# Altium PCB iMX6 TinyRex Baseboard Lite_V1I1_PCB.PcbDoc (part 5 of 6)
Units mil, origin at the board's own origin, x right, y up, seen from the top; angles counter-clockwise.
Board outline 3149.61 x 3543.31 mil, 6 copper layers (L1, L2, L3, L4 (PWR), L5, L6), stack 60.634 mil thick; 385 components, 309 nets, 1566 pads, 914 vias.
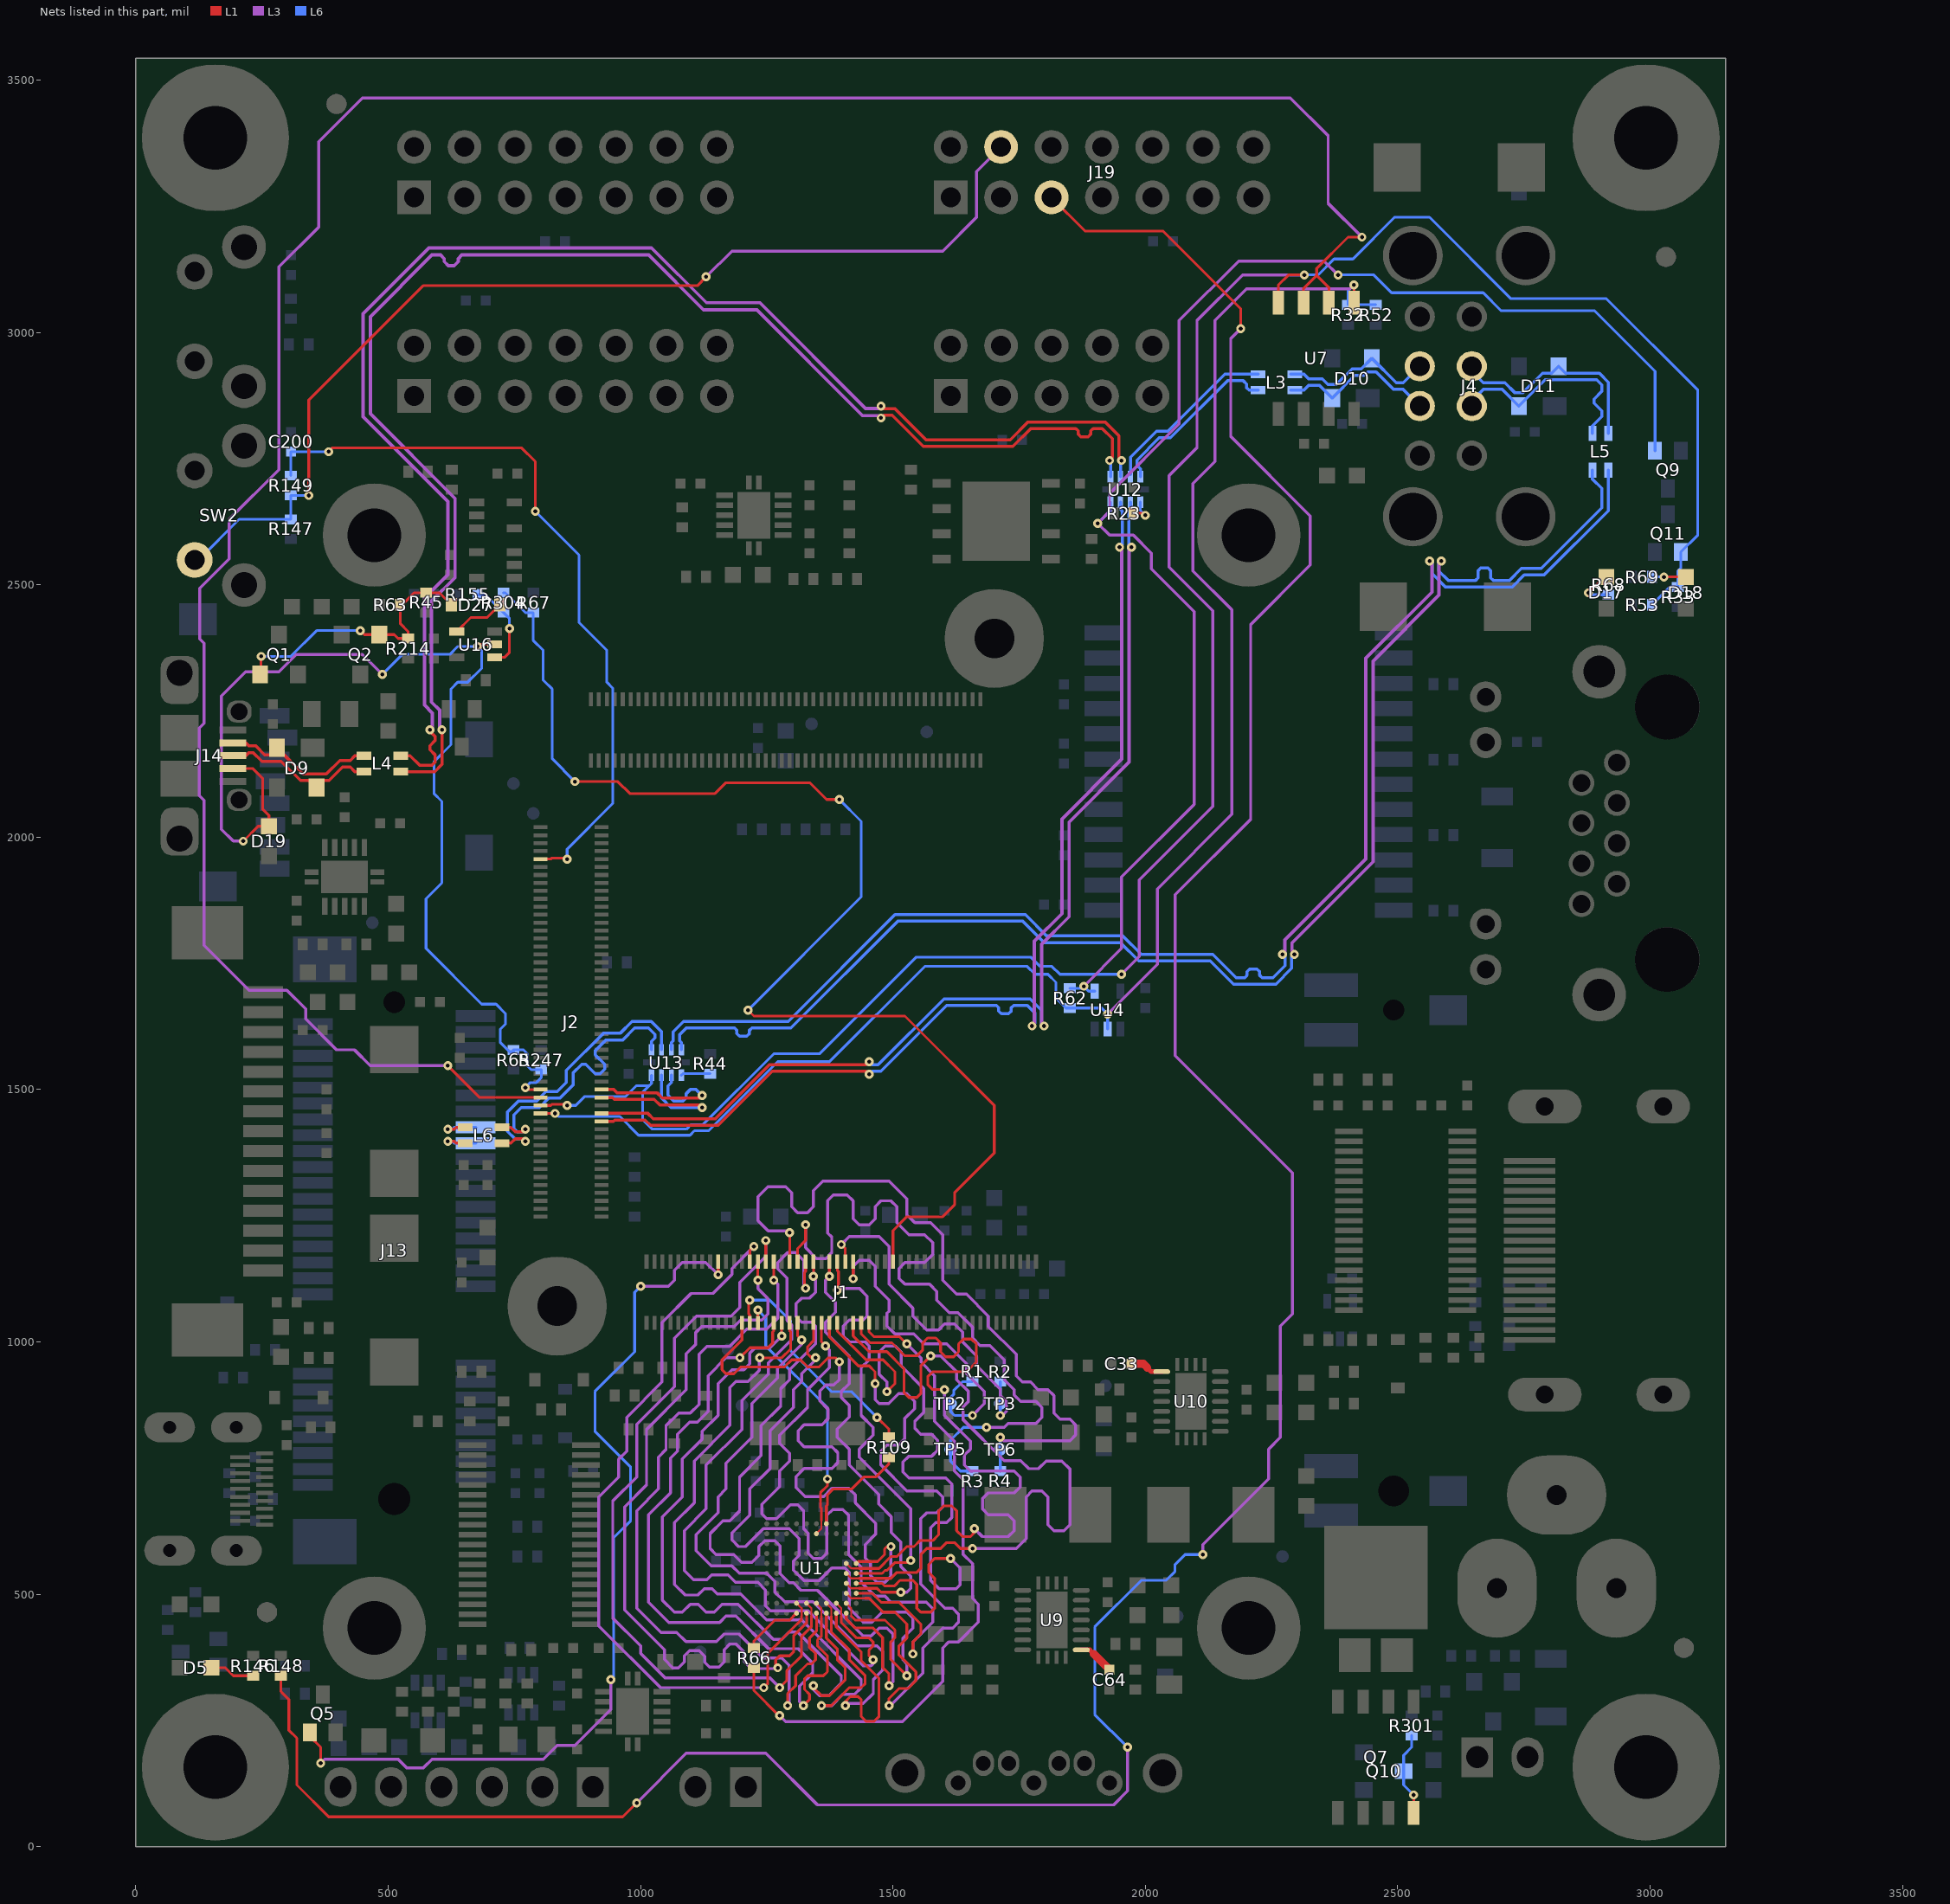
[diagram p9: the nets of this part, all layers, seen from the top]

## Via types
v1: diameter 17.72, hole 7.87, L1 to L6, 471 vias
v2: diameter 17.72, hole 7.87, L1 to L6, tented both sides, 442 vias
v3: diameter 17.72, hole 7.87, L1 to L6, tented top, 1 vias

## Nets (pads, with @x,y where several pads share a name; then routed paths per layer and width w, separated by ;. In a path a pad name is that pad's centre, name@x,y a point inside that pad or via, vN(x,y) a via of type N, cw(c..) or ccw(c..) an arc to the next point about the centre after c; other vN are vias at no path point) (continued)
USB0_CON_N: D10.2 J4.6 L3.2 | length 319
  L6 w6: L3.2@2288.39,2885.83 L3.2@2296.26,2885.83 2314.22,2885.83 2323.48,2895.08 2345.08,2895.08 D10.2@2370.08,2870.08 2414.83,2914.83 2433.2,2914.83 2440.37,2922 2457.27,2922 2492.06,2887.2 2510.82,2887.2 J4.6@2543.7,2854.33
USB0_CON_P: D10.4 J4.7 L3.1 | length 319
  L6 w6: L3.1@2288.39,2917.32 L3.1@2296.26,2917.32 2314.22,2917.32 2323.48,2908.07 2350.46,2908.07 2361.63,2896.9 2378.53,2896.9 2409.45,2927.82 2427.82,2927.82 D10.4@2448.82,2948.82 2497.44,2900.19 2510.82,2900.19 J4.7@2543.7,2933.07
USB0_ID: D19.1 J2.68 J14.4 R65.1 R247.2 U16.2 | length 2318.3
  L1 w5.4: J14.4@187.99,2135.83 J14.4@191.93,2135.83 232.03,2135.83 251.08,2116.77 251.08,2056 263.78,2043.31 D19.1@263.78,2021.65 242.13,2021.65 v1(212.6,1992.13) ; v1(677.17,2377.95) 681.1,2381.89 U16.2@710.63,2381.89 ; v1(771.65,1503.94) 775.59,1500 J2.68@801.57,1500
  L3 w5.9: v1(212.6,1992.13) 192.91,1992.13 169.29,2015.75 169.29,2279.53 217.72,2327.95 283.46,2327.95 317.72,2362.2 448.82,2362.2 v1(488.19,2322.83)
  L6 w5.4: v1(488.19,2322.83) 527.56,2362.2 622.05,2362.2 637.8,2377.95 v1(677.17,2377.95) 685.04,2370.08 685.04,2334.65 657.48,2307.09 637.8,2307.09 624.21,2293.5 624.21,2183.27 590.55,2149.61 590.55,2086.61 606.3,2070.87 606.3,1909.45 574.8,1877.95 574.8,1779.53 685.04,1669.29 713.59,1669.29 732.28,1650.6 732.28,1629.92 722.24,1619.88 722.24,1592.72 740.16,1574.8 R65.1@748.03,1574.8 ; R65.1@748.03,1578.74 767.72,1578.74 775.59,1570.87 775.59,1547.24 783.46,1539.37 R247.2@803.15,1539.37 803.15,1523.62 793.31,1513.78 781.5,1513.78 v1(771.65,1503.94)
USB0_ID_BUFF: D27.1 U16.4 | length 107.4
  L1 w5.4: U16.4@635.83,2407.48 663.58,2435.24 695.83,2435.24 D27.1@721.23,2460.63
USB0_ID_BUFF_EN: J1.38 R67.2 R304.2 | length 2529.1
  L1 w5.4: v1(870.08,2110.24) 954.98,2110.24 978.6,2086.61 1147.38,2086.61 1168.84,2108.07 1335.1,2108.07 1368.37,2074.8 v1(1393.7,2074.8) ; v1(1212.6,1657.48) 1224.41,1645.67 1523.62,1645.67 1700.79,1468.5 1700.79,1374.41 1622.05,1295.67 1622.05,1271.65 1598.43,1248.03 1527.56,1248.03 1500,1220.47 J1.38@1500,1159.06
  L6 w5.4: R304.2@728.35,2484.25 732.28,2484.25 771.65,2444.88 R67.2@787.4,2444.88 787.4,2389.76 807.09,2370.08 807.09,2311.02 825,2293.11 825,2155.31 v1(870.08,2110.24) ; v1(1212.6,1657.48) 1437.01,1881.89 1437.01,2031.5 v1(1393.7,2074.8)
USB0_ID_BUFF_EN_R: R155.1 R304.1 U16.1 | length 183.1
  L1 w5.4: U16.1@710.63,2356.3 730.31,2356.3 740.16,2366.14 v1(740.16,2413.39)
  L6 w5.4: R155.1@677.17,2480.31 692.91,2480.31 R304.1@728.35,2444.88 740.16,2433.07 v1(740.16,2413.39)
USB0_L_N: L3.3 U12.4 | length 352.7
  L6 w6: U12.4@1990.16,2714.16 1990.16,2729.57 1983.51,2736.22 1983.51,2747.29 2027.56,2791.34 2049.87,2791.34 2162.86,2904.33 2194.09,2904.33 2200.79,2897.64 2200.79,2890.5 2205.46,2885.83 L3.3@2223.43,2885.83
USB0_L_P: L3.4 U12.3 | length 354.7
  L6 w6: U12.3@1970.52,2719.04 1970.52,2752.67 2022.18,2804.33 2044.49,2804.33 2157.48,2917.32 L3.4@2223.43,2917.32
USB0_N: J2.73 U12.7 | length 2138.7
  L1 w6: J2.73@922.83,1452.76 1014.43,1452.76 1025.07,1442.12 1148.16,1442.12 1255.18,1549.14 1446.78,1549.14 v2(1452.76,1555.12)
  L3 w6.7: v2(1799.21,1625.98) 1794.55,1630.65 1794.55,1788.08 1848.95,1842.48 1848.95,2030.05 1967.78,2148.88 1967.78,2570.14 v2(1972.44,2574.8)
  L6 w6: v2(1452.76,1555.12) 1458.73,1549.14 1470.4,1549.14 1600.98,1679.72 1771.59,1679.72 1793.9,1657.42 1793.9,1631.3 v2(1799.21,1625.98) ; U12.7@1970.47,2663.79 1970.47,2649.37 1967.12,2646.02 1967.12,2580.12 v2(1972.44,2574.8)
USB0_P: J2.75 U12.8 | length 2139.5
  L1 w6: J2.75@922.83,1437.01 946.21,1437.01 948.97,1439.77 1009.05,1439.77 1019.69,1429.13 1153.54,1429.13 1260.56,1536.15 1446.78,1536.15 v2(1452.76,1530.18)
  L3 w6.7: v2(1775.59,1625.98) 1780.25,1630.65 1780.25,1794.01 1834.65,1848.4 1834.65,2035.97 1953.48,2154.81 1953.48,2570.14 v2(1948.82,2574.8)
  L6 w6: v2(1452.76,1530.18) 1458.73,1536.15 1475.79,1536.15 1606.36,1666.73 1704.72,1666.73 1709.38,1662.07 1709.38,1655.67 1714.83,1650.22 1729.07,1650.22 1734.51,1655.67 1734.51,1662.07 1739.17,1666.73 1766.21,1666.73 1780.91,1652.03 1780.91,1631.3 v2(1775.59,1625.98) ; v2(1948.82,2574.8) 1954.13,2580.12 1954.13,2646.02 1950.79,2649.37 U12.8@1950.79,2663.79
USB0_PWR_EN: J2.74 R32.1 R52.2 R62.1 U7.1 U14.2 | length 3332.7
  L1 w5.4: J2.74@801.57,1452.76 v2(830.71,1452.76) ; U7.1@2413.58,3059.06 v2@2413.58,3094.49
  L3 w5.9: v2(1925.2,1649.61) 2023.62,1748.03 2023.62,1897.64 2171.26,2045.28 2171.26,2450.79 2094.49,2527.56 2094.49,2700.79 2137.8,2744.09 2137.8,3023.62 2200.79,3086.61 2405.51,3086.61 v2(2413.39,3094.49)
  L6 w5.4: v2(830.71,1452.76) 836.81,1446.65 958.86,1446.65 996.06,1409.45 1097.7,1409.45 1106.75,1418.5 1135.04,1418.5 1271.65,1555.12 1374.02,1555.12 1562.99,1744.09 1766.01,1744.09 1781.75,1728.35 1807.09,1728.35 1822.83,1712.6 1822.83,1681.1 1842.52,1661.42 R62.1@1850.39,1661.42 1913.39,1661.42 v2(1925.2,1649.61) U14.2@1925.2,1620.08 ; v2(2413.39,3094.49) 2401.57,3082.68 R32.1@2401.57,3055.12 R52.2@2456.69,3055.12
USB0_SW_CTRL: Q9.1 R62.2 U12.9 U14.4 | length 2930.1
  L3 w5.9: v2(1877.95,1704.72) 1952.76,1779.53 1952.76,1921.26 2096.46,2064.96 2096.46,2446.85 2011.81,2531.5 2011.81,2562.99 1976.38,2598.43 1929.13,2598.43 v2(1905.51,2622.05) 1929.13,2645.67 1929.13,2681.1 2066.93,2818.9 2066.93,3023.62 2185.04,3141.73 2354.33,3141.73 v2(2381.89,3114.17)
  L6 w5.4: R62.2@1850.39,1700.79 1874.02,1700.79 v2(1877.95,1704.72) 1887.8,1694.88 U14.4@1899.61,1694.88 ; v2(1905.51,2622.05) 1931.1,2647.64 U12.9@1931.1,2663.79 ; v2(2381.89,3114.17) 2452.56,3114.17 2487.99,3078.74 2669.29,3078.74 2704.72,3043.31 2889.76,3043.31 3009.84,2923.23 Q9.1@3009.84,2765.75
USB0_SW_CTRLN_RED: D17.1 R68.1 | length 89.5
  L1 w5.4: v1(2877.95,2484.25) 2909.45,2515.75 D17.1@2913.39,2515.75
  L6 w5.4: v1(2877.95,2484.25) 2881.89,2480.31 R68.1@2917.32,2480.31
USB0_SW_EN: R23.2 U12.6 | length 55.3
  L1 w5.4: R23.2@1976.38,2641.73 1996.06,2641.73 v2(2000,2637.8)
  L6 w5.4: U12.6@1990.16,2663.79 1990.16,2647.64 v2(2000,2637.8)
USB1_CON_N: D11.2 J4.2 L5.1 | length 433
  L6 w6: J4.2@2646.85,2854.33 2646.85,2864.76 2669.29,2887.2 2707.22,2887.2 D11.2@2740.16,2854.33 D11.2@2740.16,2854.33 2792.08,2906.25 2894.28,2906.25 2904.33,2896.19 2904.33,2883.66 2888.78,2868.11 2888.78,2860.04 2904.33,2844.49 2904.33,2833.47 2885.83,2814.96 L5.1@2885.83,2800.2
USB1_CON_P: D11.4 J4.3 L5.2 | length 434
  L6 w6: J4.3@2646.85,2933.07 2646.85,2922.64 2669.29,2900.19 2712.6,2900.19 2731.64,2881.15 2748.61,2881.15 2786.7,2919.24 2805.07,2919.24 D11.4@2818.9,2933.07 2832.73,2919.24 2899.66,2919.24 2917.32,2901.57 L5.2@2917.32,2800.2
USB1_L_N: L5.4 U13.4 | length 2888.4
  L3 w6.7: v2(2295.28,1767.72) 2290.61,1772.38 2290.61,1790.61 2451.31,1951.31 2451.31,2348.95 2581.95,2479.59 2581.95,2542.58 v2(2586.61,2547.24)
  L6 w6: U13.4@1080.71,1578.86 1080.71,1593.27 1077.36,1596.62 1077.36,1608.86 1090.55,1622.05 1186.02,1622.05 1190.68,1617.39 1190.68,1610.98 1196.13,1605.54 1210.37,1605.54 1215.81,1610.98 1215.81,1617.39 1220.47,1622.05 1297.9,1622.05 1509.32,1833.47 1757.08,1833.47 1799.21,1791.34 1950.13,1791.34 1986.75,1754.73 2128.48,1754.73 2174.54,1708.66 2258.53,1708.66 2289.96,1740.09 2289.96,1762.4 v2(2295.28,1767.72) ; v2(2586.61,2547.24) 2581.3,2541.93 2581.3,2527.56 2599.8,2509.05 2654.53,2509.05 2659.19,2513.71 2659.19,2527.99 2664.63,2533.44 2678.87,2533.44 2684.32,2527.99 2684.32,2513.71 2688.98,2509.05 2721.65,2509.05 2745.27,2532.68 2784.64,2532.68 2904.33,2652.36 2904.33,2691.09 2885.83,2709.6 L5.4@2885.83,2727.36
USB1_L_P: L5.3 U13.3 | length 2887.8
  L3 w6.7: v2(2271.65,1767.72) 2276.31,1772.38 2276.31,1796.54 2437.01,1957.23 2437.01,2354.87 2567.65,2485.51 2567.65,2542.58 v2(2562.99,2547.24)
  L6 w6: U13.3@1061.02,1578.86 1061.02,1593.27 1064.37,1596.62 1064.37,1614.24 1085.17,1635.04 1292.52,1635.04 1503.94,1846.46 1762.47,1846.46 1804.59,1804.33 1955.51,1804.33 1992.13,1767.72 2133.86,1767.72 2179.92,1721.65 2196.85,1721.65 2201.51,1726.31 2201.51,1733.23 2206.95,1738.67 2221.2,1738.67 2226.64,1733.23 2226.64,1726.31 2231.3,1721.65 2253.15,1721.65 2276.97,1745.47 2276.97,1762.4 v2(2271.65,1767.72) ; v2(2562.99,2547.24) 2568.31,2541.93 2568.31,2522.18 2594.42,2496.06 2727.03,2496.06 2750.65,2519.69 2790.02,2519.69 2917.32,2646.98 L5.3@2917.32,2727.36
USB1_N: J2.67 U13.7 | length 342
  L1 w6: J2.67@922.83,1500 947.04,1500 953.19,1493.85 1032.33,1493.85 1043.31,1482.87 1116.73,1482.87 v2(1122.05,1488.19)
  L6 w6: U13.7@1061.02,1528.48 1061.02,1514.07 1054.33,1507.37 1054.33,1488.98 1065.75,1477.56 1083.86,1477.56 1090.55,1484.25 1090.55,1492.13 1098.43,1500 1110.24,1500 v2(1122.05,1488.19)
USB1_P: J2.69 U13.8 | length 340.8
  L1 w6: J2.69@922.83,1484.25 944.41,1484.25 947.81,1480.86 1026.95,1480.86 1037.93,1469.88 1116.73,1469.88 v2(1122.05,1464.57)
  L6 w6: U13.8@1041.34,1528.48 1041.34,1483.6 1060.37,1464.57 v2(1122.05,1464.57)
USB1_PWR_EN: J2.72 Q11.1 R33.1 R53.2 U7.4 U13.9 | length 4672.4
  L1 w5.4: J2.72@801.57,1468.5 821.91,1468.5 824.08,1470.67 852.17,1470.67 v2(854.33,1468.5) ; U7.4@2263.58,3047.44 U7.4@2263.58,3059.06 2263.58,3094.29 2283.46,3114.17 v2(2314.96,3114.17)
  L3 w5.9: v2(1952.76,1728.35) 1988.19,1763.78 1988.19,1915.38 2133.86,2061.04 2133.86,2448.82 2047.24,2535.43 2047.24,2716.54 2102.36,2771.65 2102.36,3023.62 2192.91,3114.17 v2(2314.96,3114.17)
  L6 w5.4: v2(854.33,1468.5) 871.52,1468.5 889.43,1486.42 970.67,1486.42 992.13,1507.87 1017.52,1507.87 ; U13.9@1021.65,1528.48 1021.65,1512.01 1017.52,1507.87 ; v2@1948.82,1724.41 v2(1952.76,1728.35) 1830.71,1728.35 1814.96,1744.09 1791.73,1744.09 1773.82,1762.01 1545.47,1762.01 1354.33,1570.87 1263.78,1570.87 1123.62,1430.71 1100,1430.71 1090.94,1421.65 1023.23,1421.65 1003.94,1440.94 1003.94,1494.29 1017.52,1507.87 ; v2(2314.96,3114.17) 2342.52,3114.17 2374.02,3145.67 2411.16,3145.67 2493.84,3228.35 2562.99,3228.35 2724.41,3066.93 2913.39,3066.93 3094.49,2885.83 3094.49,2598.43 Q11.1@3061.02,2564.96 3061.02,2533.46 3055.12,2527.56 R33.1@3055.12,2496.06 3039.37,2496.06 R53.2@3003.94,2460.63
USB1_PWR_ENN_RED: D18.1 R69.1 | length 66.9
  L1 w5.4: v1(3027.56,2515.75) D18.1@3070.87,2515.75
  L6 w5.4: R69.1@3003.94,2515.75 v1(3027.56,2515.75)
USB1_SW_EN: R44.2 U13.6 | length 58.3
  L6 w5.4: U13.6@1080.71,1528.48 1083.72,1531.5 R44.2@1137.8,1531.5
USB_MPCIE_CON_N: J13.36 L6.2 | length 92.8
  L1 w6: v1(618.11,1397.64) 630.66,1397.64 634.6,1393.7 L6.2@652.56,1393.7
  L6 w6: v1(618.11,1397.64) 626.72,1397.64 630.66,1393.7 J13.36@673.23,1393.7
USB_MPCIE_CON_P: J13.38 L6.1 | length 92.8
  L1 w6: v1(618.11,1421.26) 630.66,1421.26 634.6,1425.2 L6.1@652.56,1425.2
  L6 w6: v1(618.11,1421.26) 626.72,1421.26 630.66,1425.2 J13.38@673.23,1425.2
USB_MPCIE_N: L6.3 U13.2 | length 571.9
  L1 w6: L6.3@725.39,1393.7 743.16,1393.7 752.41,1402.95 766.34,1402.95 v2(771.65,1397.64)
  L6 w6: v2(771.65,1397.64) 766.34,1402.95 750.53,1402.95 736.22,1417.26 736.22,1455.38 758.4,1477.56 794.22,1477.56 812.59,1495.93 834.91,1495.93 853.02,1514.04 853.02,1538.06 926.38,1611.42 959.37,1611.42 982.99,1635.04 1021.13,1635.04 1041.34,1614.83 U13.2@1041.34,1578.86
USB_MPCIE_P: L6.4 U13.1 | length 573.4
  L1 w6: L6.4@725.39,1425.2 743.16,1425.2 752.41,1415.94 766.34,1415.94 v2(771.65,1421.26)
  L6 w6: v2(771.65,1421.26) 766.34,1415.94 755.91,1415.94 749.21,1422.64 749.21,1450 763.78,1464.57 799.6,1464.57 817.97,1482.94 840.29,1482.94 866.01,1508.66 866.01,1532.68 883.53,1550.2 891.61,1550.2 910.31,1531.5 919.88,1531.5 929.13,1540.75 929.13,1549.8 910.43,1568.5 910.43,1577.1 931.76,1598.43 964.75,1598.43 988.37,1622.05 1015.75,1622.05 1028.35,1609.45 1028.35,1602.36 1021.65,1595.67 U13.1@1021.65,1578.86
USB_OC: J2.70 U7.2 U7.3 | length 5057.2
  L1 w5.4: v1(618.11,1547.24) 681.1,1484.25 J2.70@801.57,1484.25 ; U7.3@2313.58,3059.06 2313.58,3087.46 2339.44,3113.32 ; U7.2@2363.58,3059.06 2363.58,3089.17 2339.44,3113.32 ; v2(2429.13,3188.98) 2401.57,3188.98 2339.44,3126.84 2339.44,3113.32
  L3 w5.9: v1(618.11,1547.24) 464.57,1547.24 433.07,1578.74 397.64,1578.74 336.61,1639.76 336.61,1659.45 299.21,1696.85 224.41,1696.85 135.43,1785.83 135.43,2073.23 125.98,2082.68 125.98,2216.54 135.43,2225.98 135.43,2384.25 126.77,2392.91 126.77,2492.91 185.04,2551.18 185.04,2629.92 283.46,2728.35 283.46,3129.92 362.2,3208.66 362.2,3377.95 448.82,3464.57 2287.4,3464.57 2362.2,3389.76 2362.2,3255.91 v2(2429.13,3188.98)
USB_OTG_CON_N: D9.2 J14.2 L4.3 | length 315.8
  L1 w6: J14.2@187.99,2187.01 217.77,2187.01 224.07,2180.71 237.66,2180.71 255.04,2163.33 265.7,2163.33 D9.2@279.53,2177.17 331.45,2125.25 377.22,2125.25 404.13,2152.16 424.55,2152.16 433.81,2161.42 L4.3@451.77,2161.42
USB_OTG_CON_P: D9.4 J14.3 L4.4 | length 315.8
  L1 w6: J14.3@187.99,2161.42 217.77,2161.42 224.07,2167.72 232.28,2167.72 249.66,2150.34 287.98,2150.34 326.07,2112.26 342.52,2112.26 356.35,2098.43 D9.4@358.27,2098.43 372.1,2112.26 382.6,2112.26 409.51,2139.17 424.55,2139.17 433.81,2129.92 L4.4@451.77,2129.92
USB_OTG_EN: D27.2 Q1.1 Q2.1 R45.2 R63.2 R214.1 | length 549.9
  L1 w5.4: Q1.1@246.06,2322.83 248.03,2324.8 v2(248.03,2358.27) ; v2(444.88,2409.45) 452.76,2401.57 Q2.1@482.28,2401.57 511.81,2401.57 519.69,2393.7 R214.1@539.37,2393.7 539.37,2407.74 523.62,2423.49 R63.2@523.62,2460.63 527.56,2460.63 551.18,2484.25 R45.2@574.8,2484.25 601.61,2484.25 D27.2@625.23,2460.63
  L6 w5.4: v2(248.03,2358.27) 307.09,2358.27 358.27,2409.45 v2(444.88,2409.45)
USB_OTG_N: L4.2 U12.2 | length 2900.3
  L1 w6: L4.2@524.61,2161.42 543.31,2161.42 561.81,2142.91 586.61,2142.91 593.31,2149.61 593.31,2162.6 582.68,2173.23 582.68,2181.3 593.31,2191.93 593.31,2199.22 582.68,2209.85 v2(582.68,2212.6) ; v2(1476.38,2854.33) 1481.69,2849.01 1504.01,2849.01 1565.62,2787.4 1732.28,2787.4 1767.72,2822.83 1919.95,2822.83 1947.44,2795.34 1947.44,2751.78 v2(1952.76,2746.47)
  L3 w6.7: v2(582.68,2212.6) 587.34,2217.26 587.34,2246.05 571.59,2261.79 571.59,2473.7 618.11,2520.22 618.11,2665.35 450.27,2833.2 450.27,3037.42 580.69,3167.84 1021.67,3167.84 1130.46,3059.06 1236.22,3059.06 1445.61,2849.67 1471.72,2849.67 v2(1476.38,2854.33)
  L6 w6: U12.2@1950.79,2714.16 1950.79,2744.5 v2(1952.76,2746.47)
USB_OTG_P: L4.1 U12.1 | length 2900.9
  L1 w6: L4.1@524.61,2129.92 591.99,2129.92 606.3,2144.23 v2(606.3,2212.6) ; v2(1476.38,2830.71) 1481.69,2836.02 1498.63,2836.02 1560.24,2774.41 1737.66,2774.41 1773.1,2809.84 1862.2,2809.84 1866.86,2805.18 1866.86,2798.78 1872.31,2793.33 1886.55,2793.33 1891.99,2798.78 1891.99,2805.18 1896.65,2809.84 1914.57,2809.84 1934.45,2789.96 1934.45,2751.78 v2(1929.13,2746.47)
  L3 w6.7: v2(606.3,2212.6) 601.64,2217.26 601.64,2251.97 585.89,2267.72 585.89,2467.78 632.41,2514.3 632.41,2671.28 464.57,2839.12 464.57,3031.5 586.61,3153.54 603.77,3153.54 610.92,3146.39 610.92,3140.59 618.79,3132.72 630.61,3132.72 638.48,3140.59 638.48,3146.35 645.67,3153.54 1015.75,3153.54 1124.54,3044.76 1230.3,3044.76 1439.68,2835.37 1471.72,2835.37 v2(1476.38,2830.71)
  L6 w6: v2(1929.13,2746.47) 1931.1,2744.5 U12.1@1931.1,2714.16
USER_BTN_HDR: J19.4 R147.1 R149.2 SW2.2 | length 2136.2
  L1 w5.4: v1(342.52,2677.17) 342.52,2866.14 569.09,3092.72 1112.4,3092.72 v1(1129.92,3110.24)
  L3 w5.9: v1(1129.92,3110.24) 1181.1,3161.42 1598.43,3161.42 1665.35,3228.35 1665.35,3318.9 J19.4@1714.17,3367.72
  L6 w5.4: SW2.2@108.46,2549.21 SW2.2@116.34,2549.21 124.02,2549.21 204.72,2629.92 R147.1@307.09,2629.92 R149.2@307.09,2677.17 v1(342.52,2677.17)
USER_BUTTON: C200.1 J2.10 R149.1 | length 1489.2
  L1 w5.4: v1(381.89,2763.78) 389.76,2771.65 763.78,2771.65 791.34,2744.09 v2(791.34,2645.67) ; J2.10@801.57,1956.69 821.91,1956.69 824.08,1958.86 852.16,1958.86 v2(854.33,1956.69)
  L6 w5.4: R149.1@307.09,2716.54 C200.1@307.09,2763.78 v1(381.89,2763.78) ; v2(791.34,2645.67) 877.95,2559.06 877.95,2425.2 933.07,2370.08 933.07,2307.09 944.88,2295.28 944.88,2066.93 854.33,1976.38 v2(854.33,1956.69)
USER_LED_BB: J1.82 Q5.1 | length 1845.3
  L1 w5.4: Q5.1@344.49,226.38 344.49,218.5 366.14,196.85 v1(366.14,165.35) ; v2(1153.54,1133.07) J1.82@1153.54,1159.06
  L3 w5.9: v1(366.14,165.35) 374.02,173.23 519.69,173.23 536.61,156.3 569.69,156.3 586.61,173.23 807.09,173.23 834.65,200.79 870.08,200.79 940.94,271.65 v1(940.94,330.71) ; v1(1000,1110.24) 1055.12,1110.24 1066.93,1122.05 1066.93,1141.73 1082.68,1157.48 1129.13,1157.48 v2(1153.54,1133.07)
  L6 w5.4: v1(940.94,330.71) 946.65,336.42 946.65,612.01 980.32,645.67 980.32,751.97 909.45,822.83 909.45,901.57 988.19,980.31 988.19,1098.43 v1(1000,1110.24)
USER_LED_HDR: J19.5 R148.1 | length 5929.6
  L1 w5.4: R148.1@287.4,338.58 287.4,307.09 303.15,291.34 303.15,230.62 318.9,214.88 318.9,122.05 381.9,59.04 964.55,59.04 v1(992.13,86.61) ; J19.5@1814.17,3267.72 1881.1,3200.79 2035.43,3200.79 2188.98,3047.24 v1(2188.98,3007.87)
  L3 w5.9: v1(992.13,86.61) 1090.55,185.04 1248.03,185.04 1350.39,82.68 1937.01,82.68 1964.76,110.43 1964.76,196.65 v1(1964.57,196.85) ; v1(2114.17,578.74) 2114.17,598.43 2244.09,728.35 2244.09,787.4 2267.72,811.02 2267.72,1031.5 2291.34,1055.12 2291.34,1334.65 2059.06,1566.93 2059.06,1885.83 2208.66,2035.43 2208.66,2421.26 2326.77,2539.37 2326.77,2636.6 2169.29,2794.08 2169.29,2988.19 v1(2188.98,3007.87)
  L6 w5.4: v1(1964.57,196.85) 1899.8,261.61 1899.8,435.24 1992.13,527.56 2041.08,527.56 2058.86,545.34 2058.86,558.86 2078.74,578.74 v1(2114.17,578.74)
USER_LED_RED: D5.1 R146.1 | length 89.2
  L1 w5.4: D5.1@149.61,354.33 177.17,354.33 192.91,338.58 R146.1@232.28,338.58
VID_IN_CSI0_D0: J1.48 R1.2 TP2.1 | length 692.9
  L1 w5.4: v2(1421.26,1125.2) J1.48@1421.26,1159.06
  L3 w5.9: v2(1421.26,1125.2) 1421.26,1149.61 1433.07,1161.42 1452.76,1161.42 1464.57,1149.61 1464.57,1110.24 1492.13,1082.68 1492.13,1060.68 1488.19,1056.74 1488.19,1031.5 1503.94,1015.75 1541.32,1015.75 1561,996.06 1606.3,996.06 1645.67,956.69 1645.67,937.01 1681.1,901.57 1681.1,877.95 v1(1657.48,854.33)
  L6 w5.4: v1(1657.48,854.33) 1622.05,854.33 1614.17,862.2 TP2.1@1614.17,877.95 1614.17,889.76 1620.28,895.87 1620.28,903.74 1637.8,921.26 R1.2@1657.48,921.26
VID_IN_CSI0_D1: J1.50 R2.2 TP3.1 | length 700.3
  L1 w5.4: v2(1397.64,1192.91) 1405.51,1185.04 J1.50@1405.51,1159.06
  L3 w5.9: v2(1397.64,1192.91) 1413.39,1208.66 1472.44,1208.66 1492.13,1188.98 1492.13,1114.17 1539.37,1066.93 1539.37,1051.18 1566.93,1023.62 1590.55,1023.62 1602.36,1035.43 1622.05,1035.43 1637.8,1019.68 1637.8,1000 1665.35,972.44 1665.35,953.59 1712.6,906.35 1712.6,893.7 1724.41,881.89 1724.41,862.2 1716.54,854.33 v1(1712.6,854.33)
  L6 w5.4: v1(1712.6,854.33) TP3.1@1712.6,877.95 R2.2@1712.6,921.26
VID_IN_CSI0_D2: J1.52 U1.F10 | length 913.7
  L1 w5.4: v2(1389.76,1102.36) 1391.93,1104.53 1391.93,1139.57 1389.76,1141.73 J1.52@1389.76,1159.06 ; U1.F10@1427.17,541.34 1478.35,541.34 1484.25,547.24 1488.19,547.24 1503.54,562.6 1531.1,562.6 v1(1535.43,566.93)
  L3 w5.9: v2(1389.76,1102.36) 1393.7,1106.3 1433.07,1106.3 1448.82,1090.55 1448.82,1051.18 1440.94,1043.31 1413.39,1043.31 1401.57,1031.5 1401.57,1011.81 1413.39,1000 1444.88,1000 1452.76,992.13 1452.76,964.57 1437.01,948.82 1437.01,854.33 1460.63,830.71 1460.63,814.96 1433.07,787.4 1433.07,771.65 1535.43,669.29 v1(1535.43,566.93)
VID_IN_CSI0_D3: J1.54 U1.G9 | length 908.1
  L1 w3.94: U1.G9@1407.48,521.65 1417.32,511.81 1433.07,511.81
  L1 w5.4: v2(1374.02,1129.92) J1.54@1374.02,1159.06 ; 1433.07,511.81 1468.5,511.81 1476.38,503.94 v1(1515.75,503.94)
  L3 w5.9: v2(1374.02,1129.92) 1366.14,1122.05 1366.14,1098.43 1385.83,1078.74 1385.83,1059.06 1366.14,1039.37 1366.14,1019.69 1413.39,972.44 1413.39,917.32 1397.64,901.57 1397.64,889.76 1413.39,874.02 1413.39,851.23 1389.76,827.6 1389.76,811.02 1413.39,787.4 1413.39,755.91 1471.46,697.83 1471.46,678.98 1496.85,653.59 1496.85,622.09 1515.75,603.2 1515.75,555.12 1535.43,535.43 1535.43,511.81 1527.56,503.94 v1(1515.75,503.94)
VID_IN_CSI0_D4: J1.51 U1.G10 | length 1512
  L1 w5.4: J1.51@1389.76,1037.8 1389.76,1021.4 1446.59,964.57 1480.32,964.57 1503.94,940.94 1503.94,917.32 v2(1488.19,901.57) ; U1.G10@1427.17,521.65 1478.35,521.65 1483.27,516.73 1503.21,516.73 1514.04,527.56 1539.37,527.56 1547.24,519.68 1547.24,472.44 1555.12,464.57 1574.8,464.57 1582.68,472.44 1582.68,531.5 1570.87,543.31 1570.87,559.06 1582.68,570.87 v1(1614.17,570.87)
  L3 w5.9: v2(1488.19,901.57) 1488.19,920.43 1472.86,935.76 1472.86,979.9 1484.67,991.71 1504.35,991.71 1516.16,979.9 1516.16,952.34 1561.02,907.48 1561.02,860.24 1543.31,842.52 1543.31,828.74 1555.12,816.93 1576.77,816.93 1588.58,805.12 1588.58,785.43 1576.77,773.62 1531.5,773.62 1519.69,761.81 1519.69,742.13 1531.5,730.31 1604.33,730.31 1616.54,718.11 1616.54,651.97 1606.3,641.73 1584.61,641.73 1574.8,631.92 1574.8,527.56 1591.34,511.02 1625.2,511.02 1633.07,518.9 1633.07,551.97 v1(1614.17,570.87)
VID_IN_CSI0_D5: J1.53 U1.H9 | length 1527.4
  L1 w3.94: U1.H9@1407.48,501.97 1417.32,492.13 1444.88,492.13
  L1 w5.4: J1.53@1374.02,1037.8 1374.02,1009.59 1431.24,952.36 1453.15,952.36 1464.57,940.94 v1(1464.57,917.32) ; 1444.88,492.13 1452.76,492.13 1480.32,464.57 1503.94,464.57 1527.56,440.94 1527.56,413.39 1511.81,397.64 1511.81,379.66 1545.47,346 1545.47,328.94 1529.78,313.25 1511.81,313.25 1492.13,293.56 v1(1492.13,279.53)
  L3 w5.9: v1(1464.57,917.32) 1464.57,885.83 1472.44,877.95 1491.29,877.95 1510.98,897.64 1527.56,897.64 1542.91,882.28 1542.91,867.74 1522.83,847.66 1522.83,807.09 1511.02,795.28 1488.19,795.28 1475.59,782.68 1475.59,756.69 1527.56,704.72 1586.61,704.72 1598.43,692.91 1598.43,673.23 1586.61,661.42 1566.93,661.42 1555.12,649.61 1555.12,520.52 1603.2,472.44 1618.11,472.44 1629.92,460.63 1629.92,444.88 1618.11,433.07 1598.43,433.07 1559.06,393.7 1559.06,343.35 1495.23,279.53 v1(1492.13,279.53)
VID_IN_CSI0_D6: J1.55 U1.H10 | length 1452
  L1 w5.4: J1.55@1358.27,1037.8 1358.27,1000 v2(1366.14,992.13) ; U1.H10@1427.17,501.97 1458.66,501.97 1476.77,483.86 1512.2,483.86 1555.12,440.94 1555.12,421.26 1539.37,405.51 v1(1539.37,381.89)
  L3 w5.9: v2(1366.14,992.13) 1374.02,984.25 1374.02,948.82 1330.71,905.51 1330.71,870.08 1275.59,814.96 1275.59,799.21 1295.28,779.53 1295.28,763.78 1275.59,744.09 1275.59,713.43 1240.16,678 1240.16,659.45 1250,649.61 1269.53,649.61 1297.09,677.17 1311.22,677.17 1323.03,665.35 1323.03,629.72 1332.28,620.47 1332.28,581.1 1342.52,570.87 1358.27,570.87 1368.9,581.5 1368.9,656.3 1380.71,668.11 1400.39,668.11 1412.2,656.3 1412.2,578.74 1437.01,553.94 1437.01,523.62 1464.57,496.06 1484.25,496.06 1496.06,484.25 1565.77,484.25 1578.74,471.29 1578.74,444.88 1539.37,405.51 v1(1539.37,381.89)
VID_IN_CSI0_D7: J1.57 U1.J9 | length 1457.2
  L1 w3.94: U1.J9@1407.48,482.28 1417.32,472.44 1417.32,456.69
  L1 w5.4: J1.57@1342.52,1037.8 1342.52,1002.23 1330.71,990.41 1330.71,976.38 1338.58,968.5 v2(1346.46,968.5) ; 1417.32,456.69 1425.2,448.82 1484.25,448.82 1503.94,429.13 1503.94,413.98 1495.47,405.51 1495.47,370.67 v1(1527.56,338.58)
  L3 w5.9: v2(1346.46,968.5) 1346.46,964.57 1318.9,937.01 1318.9,921.26 1303.15,905.51 1303.15,870.08 1256.69,823.62 1256.69,748.82 1216.58,708.71 1216.58,656.69 1181.1,621.21 1181.1,607.5 1194.11,594.49 1207.83,594.49 1243.26,629.92 1294.44,629.92 1314.17,610.19 1314.17,576.82 1303.15,565.79 1303.15,548.08 1323.67,527.56 1354.33,527.56 1378.74,551.97 1404.72,551.97 1413.39,543.31 1413.39,472.44 1440.94,444.88 1458.64,444.88 1478.33,464.57 1527.56,464.57 1539.37,452.76 1539.37,433.07 1519.69,413.39 1519.69,370.08 1527.56,362.2 v1(1527.56,338.58)
VID_IN_CSI0_D8: J1.58 U1.K9 | length 1546.4
  L1 w5.4: v2(1342.52,1129.92) J1.58@1342.52,1159.06 ; U1.K9@1407.48,462.6 1407.48,450.79 1425.2,433.07 1460.63,433.07 1479.48,414.22 1479.48,355.16 1492.13,342.52 v1(1492.13,318.9)
  L3 w5.9: v2(1342.52,1129.92) 1346.46,1125.98 1346.46,1098.43 1334.65,1086.61 1318.9,1086.61 1307.87,1075.59 1307.87,1050.39 1318.9,1039.37 1338.58,1039.37 1346.46,1031.5 1346.46,996.06 1295.28,944.88 1295.28,925.2 1277.56,907.48 1277.56,872.88 1238.58,833.9 1238.58,774.85 1196.06,732.33 1196.06,664.79 1176.95,645.67 1163.24,645.67 1137.8,620.23 1137.8,590.55 1149.61,578.74 1184.25,578.74 1200,562.99 1220.47,562.99 1234.25,576.77 1234.25,594.49 1246.06,606.3 1265.75,606.3 1276.38,595.67 1276.38,540.57 1294.12,522.83 1302.78,522.83 1317.74,507.87 1350.39,507.87 1440.94,417.32 1456.69,417.32 1472.44,433.07 1488.19,433.07 1500,421.26 1500,326.77 v1(1492.13,318.9)
VID_IN_CSI0_D9: J1.60 U1.J8 | length 1538.2
  L1 w3.94: U1.J8@1387.8,482.28 1397.64,472.44 1397.64,456.69
  L1 w5.4: v2(1326.77,1106.3) 1324.61,1108.46 1324.61,1137.34 1326.77,1139.51 J1.60@1326.77,1159.06 ; 1397.64,456.69 1397.64,443.93 1428.18,413.39 1452.76,413.39 1460.63,405.51 1460.63,397.64 1452.76,389.76 1452.76,377.95 v1(1460.63,370.08)
  L3 w5.9: v2(1326.77,1106.3) 1323.62,1109.45 1323.62,1160.63 1307.09,1177.17 1291.34,1177.17 1271.65,1157.48 1271.65,1144.84 1289.76,1126.72 1289.76,1042.89 1299.21,1033.44 1299.21,1004.77 1252.95,958.51 1252.95,936 1200.79,883.84 1200.79,826.77 1129.92,755.91 1129.92,669.29 1086.61,625.98 1086.61,547.24 1104.72,529.13 1131.5,529.13 1140.95,538.58 1173.18,538.58 1188.14,523.62 1232.28,523.62 1247.24,508.66 1247.24,477.17 1257.48,466.93 1332.28,466.93 1440.94,358.27 1456.69,358.27 1460.63,362.2 v1(1460.63,370.08)
VID_IN_CSI0_D10: J1.62 R3.2 TP5.1 | length 1516.7
  L1 w5.4: J1.62@1311.02,1159.06 1311.02,1185.04 1326.77,1200.79 v2(1326.77,1232.28)
  L3 w5.9: v2(1326.77,1232.28) 1326.77,1187.01 1348.43,1165.35 1366.93,1165.35 1378.74,1177.17 1378.74,1207.87 1370.87,1215.75 1370.87,1280.31 1381.89,1291.34 1409.45,1291.34 1421.26,1279.53 1421.26,1244.09 1433.07,1232.28 1452.76,1232.28 1464.57,1244.09 1464.57,1267.72 1476.38,1279.53 1496.06,1279.53 1507.87,1267.72 1507.87,1236.22 1531.5,1212.6 1562.99,1212.6 1578.74,1196.85 1578.74,1173.23 1562.99,1157.48 1523.62,1157.48 1511.81,1145.67 1511.81,1125.98 1523.62,1114.17 1572.49,1114.17 1586.61,1100.05 1586.61,1082.68 1611.39,1057.9 1628.76,1057.9 1657.48,1029.18 1657.48,1007.87 1672.44,992.91 1692.13,992.91 1720.47,964.57 1720.47,925.2 1740.16,905.51 1740.16,894.53 1752.8,881.89 1783.46,881.89 1795.28,870.08 1795.28,850.39 1783.46,838.58 1728.35,838.58 1720.47,830.71 v1(1685.04,830.71)
  L6 w5.4: R3.2@1657.48,744.09 1633.86,744.09 1614.17,763.78 TP5.1@1614.17,787.4 1614.17,805.31 1639.57,830.71 v1(1685.04,830.71)
VID_IN_CSI0_D11: J1.64 R4.2 TP6.1 | length 1470.9
  L1 w5.4: J1.64@1295.28,1159.06 v2(1295.28,1216.54)
  L3 w5.9: v2(1295.28,1216.54) 1292.13,1219.68 1252.76,1219.68 1232.28,1240.16 1232.28,1287.4 1251.97,1307.09 1287.4,1307.09 1299.21,1295.28 1299.21,1267.72 1311.02,1255.91 1330.71,1255.91 1342.52,1267.72 1342.52,1300.05 1361.37,1318.9 1492.13,1318.9 1527.56,1283.46 1527.56,1251.97 1543.31,1236.22 1574.8,1236.22 1598.43,1212.6 1598.43,1122.05 1625.98,1094.49 1645.67,1094.49 1688.98,1051.18 1688.98,1030.66 1744.09,975.54 1744.09,933.07 1756.69,920.47 1772.44,920.47 1787.4,905.51 1807.09,905.51 1818.9,893.7 1818.9,859.05 1830.71,847.24 1850.39,847.24 1862.2,835.43 1862.2,815.75 1850.39,803.94 1719.69,803.94 v1(1712.6,811.02)
  L6 w5.4: R4.2@1712.6,744.09 TP6.1@1712.6,787.4 v1(1712.6,811.02)
VID_IN_CSI0_D12: J1.61 U1.K8 | length 1524.3
  L1 w5.4: J1.61@1311.02,1037.8 1311.02,1011.81 v2(1318.9,1003.94) ; U1.K8@1387.8,462.6 1387.8,435.04 1437.01,385.83 1437.01,368.37 1472.44,332.93 1472.44,257.87 1462.6,248.03 1446.85,248.03 1437.01,257.87 1437.01,291.34 1430.91,297.44 1415.55,297.44 1405.51,287.4 v1(1405.51,279.53)
  L3 w5.9: v2(1318.9,1003.94) 1318.9,995.23 1271.06,947.39 1271.06,928.11 1220.47,877.52 1220.47,811.02 1169.29,759.84 1169.29,708.66 1153.54,692.91 1153.54,661.59 1110.24,618.28 1110.24,586.61 1140.16,556.69 1180.68,556.69 1195.64,541.73 1249.61,541.73 1266.14,525.2 1266.14,504.38 1285.48,485.04 1341.73,485.04 1429.13,397.64 1468.5,397.64 1479.53,386.61 1479.53,349.61 1461.02,331.1 1461.02,303.54 1440.94,283.46 1409.45,283.46 v1(1405.51,279.53)
VID_IN_CSI0_D13: J1.63 U1.J7 | length 1517.5
  L1 w3.94: U1.J7@1368.11,482.28 1377.95,472.44 1377.95,456.69
  L1 w5.4: v2(1236.22,968.5) 1279.53,968.5 1297.44,986.42 1297.44,1019.68 1295.28,1021.85 J1.63@1295.28,1037.8 ; v1(1358.27,279.53) 1377.95,279.53 1413.39,314.96 1437.01,314.96 1444.88,322.83 1444.88,338.58 1413.39,370.08 1413.39,389.76 1377.95,425.2 1377.95,456.69
  L3 w5.9: v2(1236.22,968.5) 1234.84,967.13 1234.84,943.5 1212.6,921.26 1188.98,921.26 1177.17,909.45 1177.17,834.65 1106.3,763.78 1106.3,681.1 1066.93,641.73 1066.93,519.69 1088.19,498.43 1113.43,498.43 1126.03,511.02 1141.69,511.02 1151.92,500.79 1198.01,500.79 1249.98,448.82 1318.9,448.82 1437.01,330.71 1437.01,314.96 1423.62,301.57 1400.83,301.57 1378.79,279.53 v1(1358.27,279.53)
VID_IN_CSI0_D14: J1.65 U1.K7 | length 1459.8
  L1 w5.4: v2(1279.53,1011.81) J1.65@1279.53,1037.8 ; v1(1342.52,318.9) 1342.52,314.96 1358.27,299.21 1374.02,299.21 1405.51,330.71 1405.51,354.33 1389.76,370.08 1389.76,391.73 1368.11,413.39 U1.K7@1368.11,462.6
  L3 w5.9: v2(1279.53,1011.81) 1255.26,987.54 1226.07,987.54 1216.32,977.79 1216.32,956.48 1204.72,944.88 1181.1,944.88 1153.54,917.32 1153.54,854.33 1122.05,822.83 1122.05,807.17 1082.68,767.8 1082.68,692.91 1043.31,653.54 1043.31,488.19 1066.93,464.57 1082.68,464.57 1098.43,480.31 1114.17,480.31 1129.92,464.57 1145.67,464.57 1161.42,480.31 1192.87,480.31 1262.95,410.24 1279.48,410.24 1294.44,425.2 1311.02,425.2 1397.64,338.58 1397.64,323.99 1372.86,299.21 1354.33,299.21 1342.52,311.02 v1(1342.52,318.9)
VID_IN_CSI0_D15: J1.67 U1.J6 | length 1450.8
  L1 w3.94: U1.J6@1348.43,482.28 1358.27,472.44 1358.27,456.69
  L1 w5.4: v2(1196.85,968.5) 1216.75,988.4 1252.18,988.4 1261.61,997.83 1261.61,1019.23 1263.78,1021.4 J1.67@1263.78,1037.8 ; v1(1322.83,279.53) 1334.65,291.34 1334.65,301.44 1324.61,311.48 1324.61,332.48 1330.71,338.58 1362.2,338.58 1370.08,346.46 1370.08,377.95 1350.39,397.64 1350.39,409.45 1358.27,417.32 1358.27,456.69
  L3 w5.9: v2(1196.85,968.5) 1169.29,968.5 1133.86,933.07 1133.86,862.2 1112.6,840.94 1096.85,840.94 1072.73,816.82 1072.73,783.46 1059.06,769.79 1059.06,700.79 1015.75,657.48 1015.75,484.25 1055.91,444.09 1156.69,444.09 1169.29,456.69 1188.98,456.69 1253.54,392.13 1312.6,392.13 1340.97,363.76 1340.97,344.07 1314.96,318.06 1314.96,287.4 v1(1322.83,279.53)
VID_IN_CSI0_D16: J1.68 U1.K6 | length 1532.2
  L1 w5.4: v2(1263.78,1122.05) J1.68@1263.78,1159.06 ; v1(1291.34,279.53) 1291.34,303.15 1307.09,318.9 1307.09,338.58 1330.71,362.2 1338.58,362.2 1346.46,370.08 1346.46,382.68 1334.65,394.49 1334.65,413.39 1348.43,427.17 U1.K6@1348.43,462.6
  L3 w5.9: v2(1263.78,1122.05) 1271.65,1114.17 1271.65,1047.24 1249.75,1025.34 1210.38,1025.34 1176.38,991.34 1131.12,991.34 1115.75,975.96 1115.75,876.42 1098.38,859.05 1075.59,859.05 1050.39,833.86 1050.39,786.74 1035.43,771.78 1035.43,708.66 992.13,665.35 992.13,472.44 1040.16,424.41 1071.65,424.41 1089.76,406.3 1150.39,406.3 1165.35,421.26 1194.9,421.26 1242.15,374.02 1279.53,374.02 1294.49,359.05 1294.49,282.68 v1(1291.34,279.53)
VID_IN_CSI0_D17: J1.70 U1.J5 | length 1549.4
  L1 w3.94: U1.J5@1328.74,482.28 1338.58,472.44 1338.58,456.69
  L1 w5.4: J1.70@1248.03,1159.06 v2(1248.03,1200.79) ; v1(1275.59,314.96) 1289.57,328.94 1289.57,348.62 1318.9,377.95 1318.9,416.37 1338.58,436.05 1338.58,456.69
  L3 w5.9: v2(1248.03,1200.79) 1248.03,1169.29 1196.85,1118.11 1196.85,1068.55 1179.48,1051.18 1111.07,1051.18 1066.93,1007.04 1066.93,911.4 992.13,836.59 992.13,732.28 944.88,685.04 944.88,452.76 1000,397.64 1000,382.72 1048.08,334.65 1255.91,334.65 v1(1275.59,314.96)
VID_IN_CSI0_D18: J1.72 U1.K5 | length 1491.6
  L1 w5.4: v2(1232.28,1122.05) J1.72@1232.28,1159.06 ; v1(1271.65,354.33) 1267.72,358.27 1267.72,370.08 1275.59,377.95 1295.28,377.95 1303.15,385.83 1303.15,417.32 1328.74,442.91 U1.K5@1328.74,462.6
  L3 w5.9: v2(1232.28,1122.05) 1232.28,1105.51 1251.97,1085.83 1251.97,1055.51 1239.91,1043.45 1197.96,1043.45 1185.22,1030.71 1121.26,1030.71 1109.45,1018.9 1109.45,995.28 1090.55,976.38 1090.55,905.51 1011.81,826.77 1011.81,716.54 968.5,673.23 968.5,468.55 1047.24,389.81 1047.24,370.91 1063.83,354.33 1074.8,354.33 1086.61,366.14 1086.61,377.95 1096.85,388.19 1115.75,388.19 1126.77,377.17 1126.77,365.35 1136.22,355.91 1155.12,355.91 1165.35,366.14 1165.35,389.76 1177.17,401.57 1188.98,401.57 1204.72,385.83 1204.72,368.14 1220.11,352.76 1270.08,352.76 v1(1271.65,354.33)
VID_IN_CSI0_D19: J1.74 U1.J4 | length 1517.4
  L1 w3.94: U1.J4@1309.06,482.28 1318.9,472.44 1318.9,456.69
  L1 w5.4: J1.74@1216.54,1159.06 1216.54,1181.1 v2(1224.41,1188.98) ; v1(1244.09,314.96) 1251.97,322.83 1251.97,383.4 1298.09,429.53 1318.9,450.31 1318.9,456.69
  L3 w5.9: v2(1224.41,1188.98) 1181.1,1145.67 1181.1,1133.86 1143.31,1096.06 1100.05,1096.06 1042.52,1038.54 1042.52,920.47 972.44,850.39 972.44,783.46 956.69,767.72 956.69,732.28 917.32,692.91 917.32,437.01 1039.37,314.96 v1(1244.09,314.96)
VID_IN_CSI0_DE: J1.75 U1.E10 | length 1355.3
  L1 w5.4: J1.75@1200.79,1037.8 1200.79,1003.94 1161.42,964.57 1161.42,944.88 1169.29,937.01 1185.04,937.01 1198.62,950.59 1285.24,950.59 1299.21,964.57 1316.73,964.57 1330.71,950.59 1353.88,950.59 1371.79,968.5 1385.83,968.5 v2(1393.7,960.63) ; U1.E10@1427.17,561.02 1431.1,564.96 1469.52,564.96 1483.3,578.74 1483.3,589.6 1488.19,594.49 v1(1496.06,594.49)
  L3 w5.9: v2(1393.7,960.63) 1393.7,925.2 1382.87,914.37 1367.13,914.37 1355.32,902.56 1355.32,882.87 1371.06,867.13 1371.06,847.44 1359.25,835.63 1323.82,835.63 1312.01,823.82 1312.01,804.13 1323.82,792.32 1378.94,792.32 1390.75,780.51 1390.75,760.83 1378.94,749.02 1323.82,749.02 1308.07,733.27 1308.07,711.61 1325.98,693.7 1362.99,693.7 1378.74,709.45 1412.6,709.45 1425.2,696.85 1425.2,681.1 1465.75,640.55 1465.75,619.29 1444.88,598.43 1444.88,571.67 1455.12,561.44 1455.12,537.01 1468.5,523.62 1484.25,523.62 1496.06,535.43 v1(1496.06,594.49)
VID_IN_CSI0_HS: J1.47 U1.F9 | length 1535.8
  L1 w3.94: U1.F9@1407.48,541.34 1417.32,531.5 1433.07,531.5
  L1 w5.4: J1.47@1421.26,1037.8 1421.26,1011.81 1452.36,980.71 1487.8,980.71 1521.85,946.65 1521.85,899.41 1531.5,889.76 1547.24,889.76 1555.12,897.64 1555.12,952.76 v2(1574.8,972.44) ; 1433.07,531.5 1496.06,531.5 1507.87,543.31 1547.24,543.31 1555.12,551.18 1555.12,578.74 1566.93,590.55 1594.49,590.55 1606.3,602.36 1622.05,602.36 1633.86,590.55 v1(1657.48,590.55)
  L3 w5.9: v2(1574.8,972.44) 1594.49,972.44 1625.98,940.94 1625.98,925.2 1649.61,901.57 1649.61,881.89 1638.58,870.87 1638.58,846.5 1720.52,764.57 1753.17,764.57 1768.92,748.82 1788.19,748.82 1803.54,764.17 1834.25,764.17 1850.39,748.03 1850.39,637.8 1838.58,625.98 1818.9,625.98 1807.09,637.8 1807.09,692.91 1795.28,704.72 1775.59,704.72 1763.78,692.91 1763.78,610.24 1744.09,590.55 v1(1657.48,590.55)
VID_IN_CSI0_INT: J1.73 R109.1 | length 478.6
  L1 w5.4: J1.73@1216.54,1037.8 1216.54,1052.95 1214.37,1055.12 1214.37,1080.51 v2(1216.54,1082.68) ; v1(1468.5,850.39) 1492.13,826.77 R109.1@1492.13,811.02
  L6 w5.4: v2(1216.54,1082.68) 1255.91,1082.68 1297.44,1041.14 1297.44,982.09 1377.95,901.57 1417.32,901.57 v1(1468.5,850.39)
VID_IN_CSI0_INT_R: R109.2 U1.A7 | length 218.4
  L1 w5.4: U1.A7@1368.11,639.76 1368.11,675.2 1370.08,677.17 1370.08,696.85 1381.89,708.66 1418.31,708.66 1441.94,732.28 1465.55,732.28 1492.13,758.86 R109.2@1492.13,771.65
VID_IN_CSI0_PIXCLK: J1.43 R66.1 | length 1348.1
  L1 w5.4: R66.1@1224.41,354.33 1224.41,309.31 1273.88,259.84 v1(1275.59,259.84) ; J1.43@1452.76,1037.8 1452.76,1019.68 1462.01,1010.43 1513.19,1010.43 v2(1527.56,996.06)
  L3 w5.9: v1(1275.59,259.84) 1287.4,248.03 1518.85,248.03 1598.43,327.61 1598.43,393.7 1610.24,405.51 1629.92,405.51 1669.29,444.88 1669.29,480.31 1657.48,492.13 1657.48,560.83 1638.58,579.72 1638.58,727.56 1622.05,744.09 1622.05,803.15 1582.68,842.52 1582.68,933.07 1555.91,959.84 1555.91,967.72 v2(1527.56,996.06)
VID_IN_CSI0_PIXCLK_R: R66.2 U1.K4 | length 121.1
  L1 w5.4: R66.2@1224.41,393.7 1224.41,407.22 1266.01,448.82 1295.28,448.82 U1.K4@1309.06,462.6
VID_IN_CSI0_RSTN: J1.71 U1.B6 | length 535.8
  L1 w3.94: U1.B6@1348.43,620.08 1358.27,629.92 1358.27,645.67
  L1 w5.4: J1.71@1232.28,1037.8 v2(1232.28,1062.99) ; 1358.27,645.67 1358.27,670.3 1356.3,672.27 1356.3,701.04 1370.08,714.82 v1(1370.08,728.35)
  L6 w5.4: v2(1232.28,1062.99) 1248.03,1047.24 1248.03,992.13 1370.08,870.08 v1(1370.08,728.35)
VID_IN_CSI0_VS: J1.45 U1.E9 | length 1540.4
  L1 w3.94: U1.E9@1407.48,561.02 1417.32,551.18 1433.07,551.18
  L1 w5.4: 1433.07,551.18 1472.44,551.18 1496.06,574.8 1507.87,574.8 1527.56,594.49 1541.6,594.49 1553.41,606.3 1578.74,606.3 1590.55,618.11 1590.55,665.35 1600.39,675.2 1616.14,675.2 1625.98,665.35 1625.98,625.98 1637.8,614.17 1653.54,614.17 1661.42,622.05 v1(1661.42,629.92) ; J1.45@1437.01,1037.8 1437.01,1015.75 1454.53,998.23 1497.83,998.23 1523.62,972.44 1547.24,972.44 1559.06,984.25 1559.06,997.83 1568.9,1007.68 1584.65,1007.68 1594.49,997.83 1594.49,980.32 1604.33,970.47 1620.08,970.47 1629.92,980.31 1629.92,995.87 1639.76,1005.71 1655.51,1005.71 1665.35,995.87 1665.35,960.63 1645.67,940.94 1578.74,940.94 1568.9,931.1 1568.9,915.35 1578.74,905.51 v2(1602.36,905.51)
  L3 w5.9: v2(1602.36,905.51) 1602.36,854.33 1653.54,803.15 1653.54,787.4 1641.73,775.59 1641.73,755.91 1653.54,744.09 1740.16,744.09 1751.97,732.28 1751.97,712.6 1740.16,700.79 1688.98,700.79 1677.17,688.98 1677.17,669.29 1688.98,657.48 1728.35,657.48 1740.16,645.67 1740.16,625.98 1728.35,614.17 1677.17,614.17 v1(1661.42,629.92)
VIN_CTRL: Q7.4 Q10.3 R301.2 | length 168.3
  L1 w5.4: v1(2531.5,102.36) 2531.69,102.17 Q7.4@2531.69,66.93
  L6 w5.4: R301.2@2527.56,220.47 2527.56,196.85 2511.81,181.1 Q10.3@2511.81,149.61 2511.81,122.05 v1(2531.5,102.36)
VINA_3V3: C33.1 U10.1 | length 66.6
  L1 w9.45: 2003.94,948.82 2011.81,940.94 U10.1@2032.48,940.94
  L1 w15.75: C33.1@1972.44,956.69 1996.06,956.69 2003.94,948.82
VINA_5V: C64.1 U9.1 | length 72.4
  L1 w9.45: U9.1@1873.03,389.76 1889.76,389.76 1897.64,381.89
  L1 w15.75: 1897.64,381.89 C64.1@1929.13,350.39
pads on no net: FID1.1 FID2.1 FID3.1 FID4.1 FID5.1 FID6.1 FID7.1 FID8.1 J1.25 J1.26 J1.27 J1.28 J1.31 J1.32 J1.33 J1.34 J1.37 J1.39 J1.91 J1.93 J1.97 J1.98 J1.99 J1.100 J2.1 J2.20 J2.91 J2.93 J2.97 J2.99 J3.13 J3.15 J3.17 J3.18 J3.21 J3.23 J3.24 J3.26 J3.27 J3.29 J3.30 J3.31 J3.32 J3.33 J3.34 J3.36 J3.37 J3.39 J3.40 J3.41 J3.42 J3.43 J3.44 J3.46 J3.47 J3.49 J3.51 J3.53 J3.57 J3.59 J3.61 J3.63 J3.65 J3.67 J3.81 J3.82 J3.83 J3.84 J3.85 J3.86 J3.87 J3.88 J3.89 J3.90 J3.93 J3.94 J3.95 J3.96 J3.97 J3.98 J3.99 J3.100 J5.15 J5.16 J13.3 J13.5 J13.7 J13.8 J13.10 J13.12 J13.14 J13.16 J13.17 J13.19 J13.42 J13.44 J13.45 J13.46 J13.47 J13.55 J13.56 J20.7 J20.8 U1.C9 U1.C10 U1.D9 U1.H1 U1.H2 U1.J1 U1.J2 U1.J3 U1.K1 U1.K2 U1.K3 U3.1 U4.38

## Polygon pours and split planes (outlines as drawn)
GND on L1 "Power Plane" (solid, pour order 166): 2279.53,732.28 2279.53,771.65 2314.96,771.65 2338.58,748.03 2338.58,716.54 2295.28,716.54
+5V_HDMI_IN_CON on L1 "Power Plane" (solid, pour order 118): 29 vertices, not listed, extent 259.84,775.59 358.27,929.13
+5V_FTDI on L1 "Power Plane" (solid, pour order 112): 34 vertices, not listed, extent 562.99,82.68 755.91,295.28
+3V3 on L1 "Power Plane" (solid, pour order 108): 444.88,185.04 496.06,185.04 496.06,251.97 488.19,259.84 444.88,259.84 437.01,251.97 437.01,200.79 437.01,192.91 444.88,185.04
+5V_USB_OTG on L1 "Power Plane" (solid, pour order 145): 25 vertices, not listed, extent 224.41,2157.48 515.75,2342.52
+5V_USB_OTG_Q on L1 "Power Plane" (solid, pour order 106): 303.15,2303.15 330.71,2303.15 362.21,2334.65 390,2334.65 425.2,2369.85 425.2,2379.08 425.2,2421.26 393.7,2421.26 393.7,2413.39 346.46,2366.14 326.77,2366.14 303.15,2342.52
+5V_USB_OTG_B on L1 "Power Plane" (solid, pour order 105): 267.72,2381.89 346.46,2381.89 385.83,2421.26 385.83,2472.44 354.33,2472.44 354.33,2444.88 330.71,2421.26 267.72,2421.26
+VIN on L1 "Power Plane" (solid, pour order 104): 275.59,2429.13 311.02,2429.13 322.83,2440.94 322.83,2472.44 322.83,2496.06 318.9,2500 299.21,2500 287.4,2500 271.65,2484.25 271.65,2433.07
+5V on L1 "Power Plane" (solid, pour order 103): 17 vertices, not listed, extent 401.57,2440.94 464.57,2496.06
+1V5_MPCIE on L1 "Power Plane" (solid, pour order 204): 610.24,1271.65 622.05,1271.65 625.98,1275.59 649.61,1275.59 681.1,1275.59 704.72,1299.21 708.66,1303.15 708.66,1318.9 629.92,1318.9 610.24,1299.21 610.24,1275.59
GND on L1 "Power Plane" (solid, pour order 203): 1228.35,2535.43 1240.16,2547.24 1279.53,2547.24 1283.46,2543.31 1283.46,2496.06 1279.53,2492.13 1240.16,2492.13 1228.35,2503.94
+3V3_MPCIE on L1 "Power Plane" (solid, pour order 193): 95 vertices, not listed, extent 307.09,771.65 783.46,1681.1
+3V3 on L1 "Power Plane" (solid, pour order 192): 19 vertices, not listed, extent 681.1,1141.73 783.46,1232.28
+5V_USB1_VBUS on L1 "Power Plane" (solid, pour order 189): 23 vertices, not listed, extent 2622.05,2728.35 2897.64,3374.02
GND on L1 "Power Plane" (solid, pour order 188): 2000,503.94 2000,566.93 1980.32,586.61 1944.88,586.61 1937.01,578.74 1937.01,562.99 1952.76,547.24 1952.76,523.62 1952.76,519.68 1968.5,503.94 2000,503.94
GND on L1 "Power Plane" (solid, pour order 187): 1011.81,389.76 1011.81,370.08 1031.5,350.39 1059.06,350.39 1062.99,350.39 1062.99,389.76 1070.87,397.64 1070.87,401.57 1062.99,409.45 1051.18,409.45 1039.37,397.64 1019.69,397.64
GND on L1 "Power Plane" (solid, pour order 124): 2059.06,795.28 2122.05,795.28 2122.05,949.86 2129.92,957.73 2129.92,1031.5 2090.55,1070.87 1881.89,1070.87 1881.89,996.06 2012.85,996.06 2059.06,949.86
GND on L1 "Power Plane" (solid, pour order 129): 1728.35,224.41 1905.51,224.41 1905.51,322.83 1846.46,381.89 1846.46,535.43 1783.46,535.43 1783.46,381.89 1728.35,326.77
GND on L1 "L6-No Net" (solid, pour order 130): 1295.28,606.3 1354.33,606.3 1385.83,606.3 1389.76,606.3 1389.76,594.49 1362.2,594.49 1354.33,586.61 1354.33,515.75 1362.2,507.87 1389.76,507.87 1389.76,496.06 1358.27,496.06 1295.28,496.06 1291.34,500 1291.34,602.36
GND on L1 "Power Plane" (solid, pour order 128): 2546.46,3370.87 2451.97,3370.87 2451.97,3260.63 2455.91,3256.69 2542.52,3256.69 2546.46,3260.63
GND on L1 "Power Plane" (solid, pour order 127): 2673.23,2409.45 2673.23,2503.94 2783.46,2503.94 2787.4,2500 2787.4,2413.39 2783.46,2409.45
+5V_USB0_VBUS on L1 "Power Plane" (solid, pour order 134): 17 vertices, not listed, extent 2381.89,2409.45 2519.69,2862.2
+5V on L1 "Power Plane" (solid, pour order 135): 17 vertices, not listed, extent 2334.64,2700.79 2389.76,2862.2
+1V8 on L1 "Power Plane" (solid, pour order 136): 1039.37,283.46 1086.61,283.46 1137.8,334.65 1137.8,350.39 1153.54,366.14 1177.17,366.14 1177.17,389.76 1133.86,433.07 1110.24,433.07 1102.36,433.07 1094.49,425.2 1094.49,350.39 1055.12,311.02 1039.37,311.02
GND on L1 "Power Plane" (solid, pour order 137): 70.87,1074.8 70.87,897.64 82.68,885.83 129.92,885.83 161.42,917.32 212.6,968.5 212.6,988.19 212.6,1078.74 70.87,1078.74 70.87,1074.8
+5V_MPCIE on L1 "Power Plane" (solid, pour order 138): 413.39,1594.49 362.2,1594.49 358.27,1598.43 358.27,1625.98 318.9,1665.35 318.9,1748.03 358.27,1748.03 358.27,1716.54 377.95,1696.85 377.95,1657.48 389.76,1645.67 409.45,1645.67 413.39,1641.73
+1V5_MPCIE on L1 "Power Plane" (solid, pour order 139): 523.62,1748.03 555.12,1748.03 559.06,1744.09 594.49,1708.66 594.49,1700.79 590.55,1696.85 547.24,1696.85 543.31,1696.85 523.62,1716.54 523.62,1748.03
+1V5 on L1 "Power Plane" (solid, pour order 140): 18 vertices, not listed, extent 429.13,1716.54 531.5,1862.2
GND on L1 "Power Plane" (solid, pour order 141): 531.5,1854.33 531.5,1897.64 519.69,1909.45 503.94,1909.45 488.19,1893.7 476.38,1893.7 472.44,1889.76 472.44,1877.95 496.06,1854.33
+VIN on L1 "Power Plane" (solid, pour order 142): 429.13,1980.31 456.69,1980.31 460.63,1980.31 496.06,2015.75 496.06,2035.43 480.32,2051.18 452.76,2051.18 448.82,2051.18 444.88,2047.24 444.88,2039.37 452.76,2031.5 452.76,2019.69 429.13,1996.06 429.13,1980.31
GND on L1 "Power Plane" (solid, pour order 144): 212.6,1759.84 212.6,1881.89 204.72,1889.76 204.72,1933.07 181.1,1956.69 106.3,1956.69 70.87,1921.26 70.87,1759.84 78.74,1759.84 106.3,1759.84
GND on L1 "Power Plane" (solid, pour order 146): 405.51,2271.65 405.51,2216.54 464.57,2216.54 468.5,2220.47 468.5,2267.72 464.57,2271.65 405.51,2271.65
GND on L1 "Power Plane" (solid, pour order 126): 559.06,915.75 464.57,915.75 464.57,1025.98 468.5,1029.92 555.12,1029.92 559.06,1025.98
GND on L1 "Power Plane" (solid, pour order 125): 559.06,1289.76 464.57,1289.76 464.57,1400 468.5,1403.94 555.12,1403.94 559.06,1400
+VIN on L1 "Power Plane" (solid, pour order 150): 18 vertices, not listed, extent 1602.36,405.51 1755.91,500
GND on L1 "Power Plane" (solid, pour order 151): 2094.49,279.53 2106.3,291.34 2106.3,311.02 2082.68,334.65 2015.75,334.65 2015.75,279.53
+5V on L1 "Power Plane" (solid, pour order 152): 19 vertices, not listed, extent 1874.02,374.02 2074.8,492.13
GND on L1 "Power Plane" (solid, pour order 153): 2035.43,503.94 2066.93,503.94 2086.61,523.62 2086.61,551.18 2078.74,559.06 2031.5,559.06 2027.56,555.12 2027.56,531.5 2027.56,511.81 2035.43,503.94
